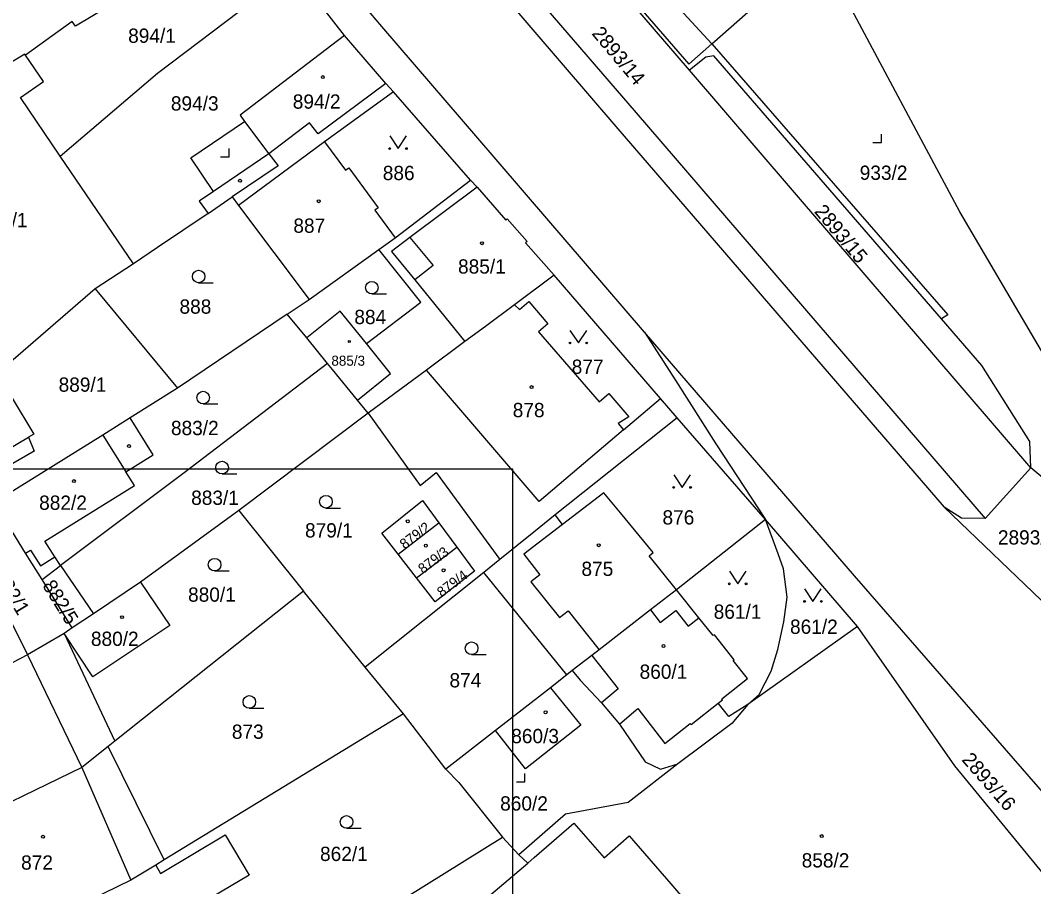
# Model space of a CAD drawing. Extents: x -496682 to -495907, y -1088575 to -1088018.
# Drawn here: x -496196 to -496075.2, y -1088214 to -1088110.8 of the extents above; entities that cross this region are included whole.
import ezdxf

# ---------------------------------------------------------------- set-up
doc = ezdxf.new("R2010")
doc.units = 0
for name, color, linetype in [('Hranice parcel', 7, 'Continuous'), ('Parcelní čísla', 7, 'Continuous'), ('Vnitřní kresba', 7, 'Continuous'), ('Vrstva 63', 7, 'Continuous'), ('Značky budov', 7, 'Continuous'), ('Značky kultur', 7, 'Continuous')]:
    doc.layers.add(name, color=color, linetype=linetype)

msp = doc.modelspace()

# ---------------------------------------------------------------- linework, layer by layer
at = {"layer": 'Hranice parcel'}
for p, q in [((-496113.57, -1088113.57), (-496117.39, -1088109.46)), ((-496152.45, -1088118.29), (-496157.35, -1088112.6)), ((-496075.55, -1088164.09), (-496116.26, -1088116.72)), ((-496151.53, -1088119.31), (-496152.45, -1088118.29)), ((-496142.34, -1088129.81), (-496151.53, -1088119.31)), ((-496182.51, -1088139.79), (-496191.24, -1088126.97)), ((-496151.33, -1088136.69), (-496142.34, -1088129.81)), ((-496153.28, -1088138.08), (-496151.33, -1088136.69)), ((-496161.59, -1088144.03), (-496153.28, -1088138.08)), ((-496182.51, -1088139.79), (-496187.08, -1088142.78)), ((-496132.39, -1088141.15), (-496137.12, -1088144.68)), ((-496119.71, -1088155.84), (-496132.39, -1088141.15)), ((-496187.08, -1088142.78), (-496198.32, -1088152.5)), ((-496187.08, -1088142.78), (-496177.27, -1088154.6)), ((-496164.19, -1088145.79), (-496161.59, -1088144.03)), ((-496164.19, -1088145.79), (-496177.27, -1088154.6)), ((-496161.87, -1088148.63), (-496164.19, -1088145.79)), ((-496159.38, -1088151.68), (-496161.87, -1088148.63)), ((-496177.27, -1088154.6), (-496182.92, -1088158.15)), ((-496154.55, -1088157.61), (-496155.82, -1088156.05)), ((-496117.71, -1088158.15), (-496119.71, -1088155.84)), ((-496154.55, -1088157.61), (-496169.94, -1088169.21)), ((-496117.71, -1088158.15), (-496132.27, -1088169.7)), ((-496107.18, -1088170.28), (-496117.71, -1088158.15)), ((-496081, -1088170.14), (-496075.55, -1088164.09)), ((-496065.92, -1088172.25), (-496075.55, -1088164.09)), ((-496169.94, -1088169.21), (-496181.67, -1088177.72)), ((-496169.94, -1088169.21), (-496162.24, -1088178.79)), ((-496085.88, -1088168.81), (-496073.38, -1088180.81)), ((-496150.97, -1088174.38), (-496146.11, -1088170.67)), ((-496146.11, -1088170.67), (-496143.99, -1088173.55)), ((-496107.18, -1088170.28), (-496117.81, -1088178.66)), ((-496096.21, -1088183.01), (-496107.18, -1088170.28)), ((-496148.77, -1088177.22), (-496143.99, -1088173.55)), ((-496148.77, -1088177.22), (-496150.97, -1088174.38)), ((-496138.84, -1088175.04), (-496140.75, -1088176.58)), ((-496193.41, -1088177.4), (-496191.21, -1088175.76)), ((-496191.21, -1088175.76), (-496187.29, -1088181.5)), ((-496140.75, -1088176.58), (-496154.9, -1088187.88)), ((-496130.86, -1088188.79), (-496140.75, -1088176.58)), ((-496189.82, -1088183.19), (-496193.41, -1088177.4)), ((-496181.67, -1088177.72), (-496187.29, -1088181.5)), ((-496162.24, -1088178.79), (-496184.73, -1088196.69)), ((-496154.9, -1088187.88), (-496162.24, -1088178.79)), ((-496187.29, -1088181.5), (-496189.82, -1088183.19)), ((-496190.77, -1088183.83), (-496195.13, -1088186.39)), ((-496189.82, -1088183.19), (-496190.77, -1088183.83)), ((-496190.77, -1088183.83), (-496184.73, -1088196.69)), ((-496096.21, -1088183.01), (-496109.3, -1088192.3)), ((-496195.13, -1088186.39), (-496199.29, -1088188.52)), ((-496150.33, -1088193.43), (-496154.9, -1088187.88)), ((-496130.86, -1088188.79), (-496132.79, -1088190.31)), ((-496130.21, -1088188.26), (-496130.86, -1088188.79)), ((-496150.33, -1088193.43), (-496178.87, -1088210.84)), ((-496145.28, -1088200.01), (-496150.33, -1088193.43)), ((-496139.35, -1088195.4), (-496145.28, -1088200.01)), ((-496184.73, -1088196.69), (-496185.54, -1088197.33)), ((-496178.87, -1088210.84), (-496185.54, -1088197.33)), ((-496162.6, -1088223.08), (-496138.52, -1088208.12)), ((-496138.52, -1088208.12), (-496136.58, -1088210.21)), ((-496136.58, -1088210.21), (-496135.52, -1088211.22)), ((-496178.87, -1088210.84), (-496179.86, -1088211.45))]:
    msp.add_line(p, q, dxfattribs=at)
for points in [[(-496121.59, -1088147.94), (-496135.68, -1088131.58), (-496139.54, -1088127.1), (-496152.9, -1088111.52), (-496154.28, -1088109.93), (-496192.25, -1088065.81), (-496197.08, -1088060.92), (-496210.28, -1088048.82), (-496224.09, -1088036.2), (-496238.46, -1088023.17), (-496242.49, -1088019.49)], [(-496181.15, -1088019.49), (-496180.97, -1088024.95), (-496179.9, -1088035.45), (-496177.55, -1088046.36), (-496174.16, -1088056.24), (-496169.6, -1088065.68), (-496164.16, -1088074.78), (-496158.66, -1088082.86), (-496152.68, -1088090.79), (-496145.28, -1088099.81), (-496124.8, -1088123.7), (-496085.88, -1088168.81)], [(-496116.26, -1088116.72), (-496137.09, -1088092.45), (-496144.2, -1088083.68), (-496150.73, -1088075.21), (-496154.49, -1088069.71), (-496160.82, -1088074.53), (-496156.15, -1088081.34), (-496150.43, -1088088.98), (-496143.13, -1088097.97), (-496122.6, -1088121.81), (-496081, -1088170.14)], [(-496063.87, -1088167.88), (-496084, -1088133.61), (-496098.14, -1088107.2), (-496102.25, -1088098.03)], [(-496129.35, -1088100.96), (-496116.34, -1088116.02), (-496113.57, -1088113.57)], [(-496113.57, -1088113.57), (-496105.32, -1088106.28), (-496108.99, -1088102.12)], [(-496191.24, -1088126.97), (-496179.64, -1088117.06), (-496163.37, -1088104.73)], [(-496157.35, -1088112.6), (-496159.89, -1088109.34), (-496159.74, -1088109.21), (-496163.37, -1088104.73)], [(-496183.44, -1088107.88), (-496189.41, -1088111.49), (-496189.82, -1088110.92), (-496195.38, -1088114.92)], [(-496157.35, -1088112.6), (-496169.82, -1088122.1), (-496169.28, -1088122.83), (-496166.37, -1088126.68)], [(-496113.57, -1088113.57), (-496085.45, -1088145.89), (-496086.2, -1088146.36)], [(-496195.38, -1088114.92), (-496195.47, -1088114.8), (-496200.29, -1088117.66), (-496201.65, -1088118.63)], [(-496191.24, -1088126.97), (-496196, -1088119.97), (-496193.23, -1088118.07), (-496195.38, -1088114.92)], [(-496086.2, -1088146.36), (-496113.33, -1088115), (-496114.3, -1088115.18), (-496116.26, -1088116.72)], [(-496152.45, -1088118.29), (-496160.5, -1088124.31), (-496161.54, -1088123.01), (-496166.37, -1088126.68)], [(-496151.53, -1088119.31), (-496159.75, -1088125.24), (-496157.24, -1088128.65), (-496156.86, -1088128.37), (-496153.36, -1088133.14), (-496153.74, -1088133.42), (-496151.33, -1088136.69)], [(-496166.37, -1088126.68), (-496172.98, -1088131.17), (-496174.67, -1088132.32), (-496173.63, -1088133.79)], [(-496142.34, -1088129.81), (-496141.55, -1088130.68), (-496138.15, -1088134.58), (-496137.97, -1088134.42), (-496135.59, -1088137.14), (-496135.77, -1088137.3), (-496132.39, -1088141.15)], [(-496173.63, -1088133.79), (-496170.75, -1088131.83), (-496169.99, -1088132.84), (-496161.59, -1088144.03)], [(-496173.63, -1088133.79), (-496179.66, -1088137.84), (-496182.51, -1088139.79)], [(-496154.75, -1088149.3), (-496148.28, -1088144.35), (-496153.28, -1088138.08)], [(-496137.12, -1088144.68), (-496140.55, -1088147.25), (-496143.01, -1088149.07), (-496147.58, -1088152.46), (-496154.55, -1088157.61)], [(-496137.12, -1088144.68), (-496136.49, -1088145.23), (-496135.4, -1088144.29), (-496133.14, -1088146.93), (-496134.25, -1088147.92), (-496127, -1088156.24), (-496125.87, -1088155.26), (-496123.48, -1088158.01), (-496124.75, -1088158.81), (-496124.12, -1088159.59), (-496119.71, -1088155.84)], [(-496154.75, -1088149.3), (-496157.87, -1088145.45), (-496161.87, -1088148.63)], [(-496075.55, -1088164.09), (-496075.66, -1088160.98), (-496081.4, -1088151.92), (-496086.2, -1088146.36)], [(-496036.91, -1088246.54), (-496039.16, -1088242.24), (-496043.62, -1088236.85), (-496051.67, -1088227.99), (-496069.06, -1088208.54), (-496096.57, -1088176.99), (-496121.59, -1088147.94)], [(-496121.59, -1088147.94), (-496117.88, -1088153.72), (-496113.1, -1088161.25), (-496107.18, -1088170.28)], [(-496155.82, -1088156.05), (-496151.87, -1088152.87), (-496154.75, -1088149.3)], [(-496198.32, -1088152.5), (-496196.96, -1088155.81), (-496194.39, -1088160.08), (-496195.03, -1088160.46), (-496194.34, -1088162.14), (-496196.89, -1088163.58), (-496199.54, -1088165.08)], [(-496159.38, -1088151.68), (-496176.46, -1088164.72), (-496191.21, -1088175.76)], [(-496155.82, -1088156.05), (-496158.8, -1088152.4), (-496159.38, -1088151.68)], [(-496182.92, -1088158.15), (-496186.17, -1088160.2), (-496199.12, -1088168.24)], [(-496191.21, -1088175.76), (-496191.91, -1088174.73), (-496193.08, -1088172.85), (-496182.41, -1088166.22), (-496183.43, -1088164.59), (-496180.18, -1088162.57), (-496182.92, -1088158.15)], [(-496154.55, -1088157.61), (-496148.33, -1088166.2), (-496146.42, -1088164.68), (-496138.84, -1088175.04)], [(-496193.41, -1088177.4), (-496195.37, -1088174.27), (-496199.12, -1088168.24)], [(-496150.97, -1088174.38), (-496152.91, -1088171.88), (-496148.07, -1088167.99), (-496146.11, -1088170.67)], [(-496117.81, -1088178.66), (-496121.03, -1088174.58), (-496120.57, -1088174.2), (-496124.47, -1088169.46), (-496126.44, -1088167.07), (-496131.38, -1088170.86), (-496132.27, -1088169.7)], [(-496081, -1088170.14), (-496083.82, -1088170.09), (-496085.88, -1088168.81)], [(-496132.27, -1088169.7), (-496134.8, -1088171.76), (-496138.84, -1088175.04)], [(-496109.3, -1088192.3), (-496107.94, -1088191.13), (-496106.49, -1088188.34), (-496105.71, -1088185.74), (-496104.98, -1088182.44), (-496104.61, -1088179.52), (-496105.03, -1088176.16), (-496105.67, -1088174.35), (-496107.18, -1088170.28)], [(-496207.04, -1088172.83), (-496204.16, -1088172.47), (-496201.5, -1088173.7), (-496195.13, -1088186.39)], [(-496143.99, -1088173.55), (-496141.88, -1088176.43), (-496146.57, -1088180.06), (-496148.77, -1088177.22)], [(-496181.67, -1088177.72), (-496178.17, -1088182.88), (-496187.37, -1088189), (-496190.77, -1088183.83)], [(-496117.81, -1088178.66), (-496120.89, -1088181.04), (-496126.99, -1088185.79), (-496127.9, -1088186.49), (-496130.21, -1088188.26)], [(-496109.3, -1088192.3), (-496111.56, -1088193.75), (-496112.82, -1088192.16), (-496112.3, -1088191.76), (-496112.4, -1088191.64), (-496109.33, -1088189.23), (-496111.05, -1088187.07), (-496110.92, -1088186.97), (-496113.28, -1088184), (-496113.41, -1088184.1), (-496115.11, -1088181.97), (-496117.81, -1088178.66)], [(-496071.36, -1088215.79), (-496084.6, -1088199.6), (-496096.21, -1088183.01)], [(-496130.21, -1088188.26), (-496129.29, -1088189.41), (-496126.73, -1088192.13), (-496124.59, -1088194.64), (-496121.54, -1088199.13), (-496119.68, -1088200), (-496117.65, -1088199.4)], [(-496132.79, -1088190.31), (-496129.18, -1088194.79), (-496135.77, -1088199.99), (-496139.35, -1088195.4)], [(-496132.79, -1088190.31), (-496133.9, -1088191.16), (-496139.35, -1088195.4)], [(-496109.3, -1088192.3), (-496111.2, -1088194.59), (-496117.65, -1088199.4)], [(-496185.54, -1088197.33), (-496188.66, -1088199.81), (-496204.1, -1088207.28)], [(-496117.65, -1088199.4), (-496123.55, -1088204), (-496131.03, -1088205.37), (-496136.58, -1088210.21)], [(-496145.28, -1088200.01), (-496143.73, -1088201.59), (-496138.52, -1088208.12)], [(-496135.52, -1088211.22), (-496134.74, -1088210.55), (-496130.01, -1088206.47), (-496126.43, -1088210.59), (-496123.42, -1088207.95), (-496118.45, -1088213.69), (-496114.82, -1088217.94), (-496115.42, -1088218.43), (-496112.79, -1088220.23), (-496111.62, -1088221.6), (-496111.79, -1088223.84), (-496113.66, -1088225.45)], [(-496179.86, -1088211.45), (-496179.28, -1088212.43), (-496171.58, -1088207.84), (-496168.73, -1088212.63), (-496176.42, -1088217.23), (-496169.35, -1088226.74)], [(-496179.86, -1088211.45), (-496182.82, -1088213.25), (-496186.02, -1088214.8), (-496198.35, -1088220.77)], [(-496140.48, -1088227.9), (-496138.4, -1088226.02), (-496144.6, -1088218.93), (-496135.52, -1088211.22)]]:
    msp.add_lwpolyline(points, dxfattribs=at)
at = {"layer": 'Vnitřní kresba'}
for p, q in [((-496175.69, -1088127.18), (-496169.28, -1088122.83)), ((-496159.75, -1088125.24), (-496169.99, -1088132.84)), ((-496172.98, -1088131.17), (-496175.69, -1088127.18)), ((-496166.37, -1088126.68), (-496165.28, -1088128.11)), ((-496165.28, -1088128.11), (-496170.75, -1088131.83)), ((-496141.55, -1088130.68), (-496149.57, -1088136.67)), ((-496149.57, -1088136.67), (-496151.77, -1088138.32)), ((-496149.57, -1088136.67), (-496146.8, -1088139.98)), ((-496151.77, -1088138.32), (-496148.99, -1088141.72)), ((-496146.8, -1088139.98), (-496148.99, -1088141.72)), ((-496148.99, -1088141.72), (-496143.01, -1088149.07)), ((-496134.15, -1088168.11), (-496147.58, -1088152.46)), ((-496124.12, -1088159.59), (-496134.15, -1088168.11)), ((-496197.78, -1088162.1), (-496195.03, -1088160.46)), ((-496186.17, -1088160.2), (-496183.43, -1088164.59)), ((-496131.38, -1088170.86), (-496135.99, -1088174.39)), ((-496195.37, -1088174.27), (-496194.78, -1088173.9)), ((-496194.78, -1088173.9), (-496193.61, -1088175.79)), ((-496193.61, -1088175.79), (-496191.91, -1088174.73)), ((-496135.99, -1088174.39), (-496134.09, -1088176.86)), ((-496134.09, -1088176.86), (-496135.16, -1088177.71)), ((-496135.16, -1088177.71), (-496131.72, -1088181.96)), ((-496131.72, -1088181.96), (-496130.69, -1088181.14)), ((-496130.69, -1088181.14), (-496126.99, -1088185.79)), ((-496120.89, -1088181.04), (-496119.72, -1088182.53)), ((-496119.72, -1088182.53), (-496117.89, -1088181.1)), ((-496117.89, -1088181.1), (-496116.41, -1088182.97)), ((-496116.41, -1088182.97), (-496115.11, -1088181.97)), ((-496195.13, -1088186.39), (-496188.66, -1088199.81)), ((-496127.9, -1088186.49), (-496126.37, -1088188.36)), ((-496126.37, -1088188.36), (-496124.76, -1088190.44)), ((-496124.76, -1088190.44), (-496126.73, -1088192.13)), ((-496116.06, -1088194.7), (-496112.82, -1088192.16)), ((-496124.59, -1088194.64), (-496122.61, -1088192.94)), ((-496122.61, -1088192.94), (-496122.41, -1088192.78)), ((-496122.41, -1088192.78), (-496119.19, -1088196.94)), ((-496119.19, -1088196.94), (-496116.16, -1088194.58)), ((-496116.16, -1088194.58), (-496116.06, -1088194.7)), ((-496188.66, -1088199.81), (-496182.82, -1088213.25))]:
    msp.add_line(p, q, dxfattribs=at)
at = {"layer": 'Vrstva 63'}
msp.add_lwpolyline([(-496137.35, -1088164.24), (-496137.35, -1088461.24), (-496557.35, -1088461.24), (-496557.35, -1088164.24)], close=True, dxfattribs=at)
at = {"layer": 'Značky budov'}
for centre, radius in [((-496159.95, -1088117.54), 0.175), ((-496169.82, -1088129.9), 0.175), ((-496160.43, -1088132.34), 0.175), ((-496140.98, -1088137.34), 0.175), ((-496156.79, -1088149.06), 0.117), ((-496135.07, -1088154.49), 0.175), ((-496183.05, -1088161.52), 0.175), ((-496189.62, -1088165.69), 0.175), ((-496149.83, -1088170.48), 0.175), ((-496147.67, -1088173.38), 0.175), ((-496127.06, -1088173.33), 0.175), ((-496145.55, -1088176.32), 0.175), ((-496183.87, -1088181.9), 0.175), ((-496119.34, -1088185.34), 0.175), ((-496133.4, -1088193.24), 0.175), ((-496193.3, -1088208.07), 0.175), ((-496100.48, -1088207.99), 0.175)]:
    msp.add_circle(centre, radius, dxfattribs=at)
at = {"layer": 'Značky kultur'}
for p, q in [((-496093.37, -1088125.34), (-496093.37, -1088124.34)), ((-496094.37, -1088125.34), (-496093.37, -1088125.34)), ((-496172.13, -1088127.05), (-496171.13, -1088127.05)), ((-496171.13, -1088127.05), (-496171.13, -1088126.05)), ((-496174.75, -1088142.06), (-496173, -1088142.06)), ((-496154.11, -1088143.39), (-496152.36, -1088143.39)), ((-496174.21, -1088156.49), (-496172.46, -1088156.49)), ((-496171.96, -1088164.83), (-496170.21, -1088164.83)), ((-496159.58, -1088168.9), (-496157.83, -1088168.9)), ((-496172.85, -1088176.4), (-496171.1, -1088176.4)), ((-496142.22, -1088186.36), (-496140.47, -1088186.36)), ((-496168.71, -1088192.75), (-496166.96, -1088192.75)), ((-496135.86, -1088201.53), (-496135.86, -1088200.53)), ((-496136.86, -1088201.53), (-496135.86, -1088201.53)), ((-496157.12, -1088207.05), (-496155.37, -1088207.05))]:
    msp.add_line(p, q, dxfattribs=at)
for points in [[(-496151.98, -1088124.56), (-496150.98, -1088126.06), (-496149.98, -1088124.56)], [(-496130.49, -1088147.73), (-496129.49, -1088149.23), (-496128.49, -1088147.73)], [(-496118.12, -1088164.94), (-496117.12, -1088166.44), (-496116.12, -1088164.94)], [(-496111.49, -1088176.43), (-496110.49, -1088177.93), (-496109.49, -1088176.43)], [(-496102.53, -1088178.53), (-496101.53, -1088180.03), (-496100.53, -1088178.53)]]:
    msp.add_lwpolyline(points, dxfattribs=at)
for centre, radius in [((-496151.98, -1088126.06), 0.1), ((-496149.98, -1088126.06), 0.1), ((-496174.75, -1088141.31), 0.75), ((-496154.11, -1088142.64), 0.75), ((-496130.49, -1088149.23), 0.1), ((-496128.49, -1088149.23), 0.1), ((-496174.21, -1088155.74), 0.75), ((-496171.96, -1088164.08), 0.75), ((-496118.12, -1088166.44), 0.1), ((-496116.12, -1088166.44), 0.1), ((-496159.58, -1088168.15), 0.75), ((-496172.85, -1088175.65), 0.75), ((-496111.49, -1088177.93), 0.1), ((-496109.49, -1088177.93), 0.1), ((-496102.53, -1088180.03), 0.1), ((-496100.53, -1088180.03), 0.1), ((-496142.22, -1088185.61), 0.75), ((-496168.71, -1088192), 0.75), ((-496157.12, -1088206.3), 0.75)]:
    msp.add_circle(centre, radius, dxfattribs=at)

# ---------------------------------------------------------------- texts
at = {"layer": 'Parcelní čísla'}
for s, height, p in [('894/1', 1.7, (-496183.15, -1088113.46)), ('894/3', 1.7, (-496178.06, -1088121.53)), ('894/2', 1.7, (-496163.53, -1088121.31)), ('886', 1.7, (-496152.8, -1088129.82)), ('933/2', 1.7, (-496095.95, -1088129.79)), ('893/1', 1.7, (-496200.83, -1088135.43)), ('887', 1.7, (-496163.46, -1088136.1)), ('885/1', 1.7, (-496143.83, -1088140.96)), ('888', 1.7, (-496177.03, -1088145.74)), ('884', 1.7, (-496156.19, -1088146.98)), ('885/3', 1.2, (-496158.93, -1088151.94)), ('877', 1.7, (-496130.28, -1088152.91)), ('889/1', 1.7, (-496191.44, -1088155.04)), ('878', 1.7, (-496137.31, -1088158.07)), ('883/2', 1.7, (-496178.05, -1088160.21)), ('883/1', 1.7, (-496175.64, -1088168.52)), ('882/2', 1.7, (-496193.76, -1088169.11)), ('876', 1.7, (-496119.46, -1088170.86)), ('879/1', 1.7, (-496162.07, -1088172.41)), ('2893/31', 1.7, (-496079.48, -1088173.25)), ('875', 1.7, (-496129.12, -1088176.99)), ('880/1', 1.7, (-496176.01, -1088180.06)), ('861/1', 1.7, (-496113.36, -1088182.1)), ('861/2', 1.7, (-496104.26, -1088183.89)), ('880/2', 1.7, (-496187.59, -1088185.33)), ('860/1', 1.7, (-496122.19, -1088189.25)), ('874', 1.7, (-496144.85, -1088190.27)), ('873', 1.7, (-496170.79, -1088196.4)), ('860/3', 1.7, (-496137.49, -1088196.92)), ('860/2', 1.7, (-496138.81, -1088204.95)), ('862/1', 1.7, (-496160.28, -1088210.96)), ('872', 1.7, (-496195.91, -1088211.99)), ('858/2', 1.7, (-496102.87, -1088211.73))]:
    msp.add_text(s, height=height, dxfattribs=at).set_placement(p)
for s, height, rotation, p in [('2893/14', 1.7, 310, (-496127.97, -1088112.38)), ('2893/15', 1.7, 310, (-496101.45, -1088133.6)), ('879/2', 1.2, 37, (-496150.21, -1088173.85)), ('879/3', 1.2, 37, (-496148.02, -1088176.79)), ('882/1', 1.7, 301, (-496199.19, -1088176.94)), ('879/4', 1.2, 37, (-496145.77, -1088179.57)), ('882/5', 1.7, 302, (-496193.43, -1088178.13)), ('2893/16', 1.7, 311, (-496083.87, -1088198.94))]:
    msp.add_text(s, height=height, rotation=rotation, dxfattribs=at).set_placement(p)

doc.saveas('drawing.dxf')
